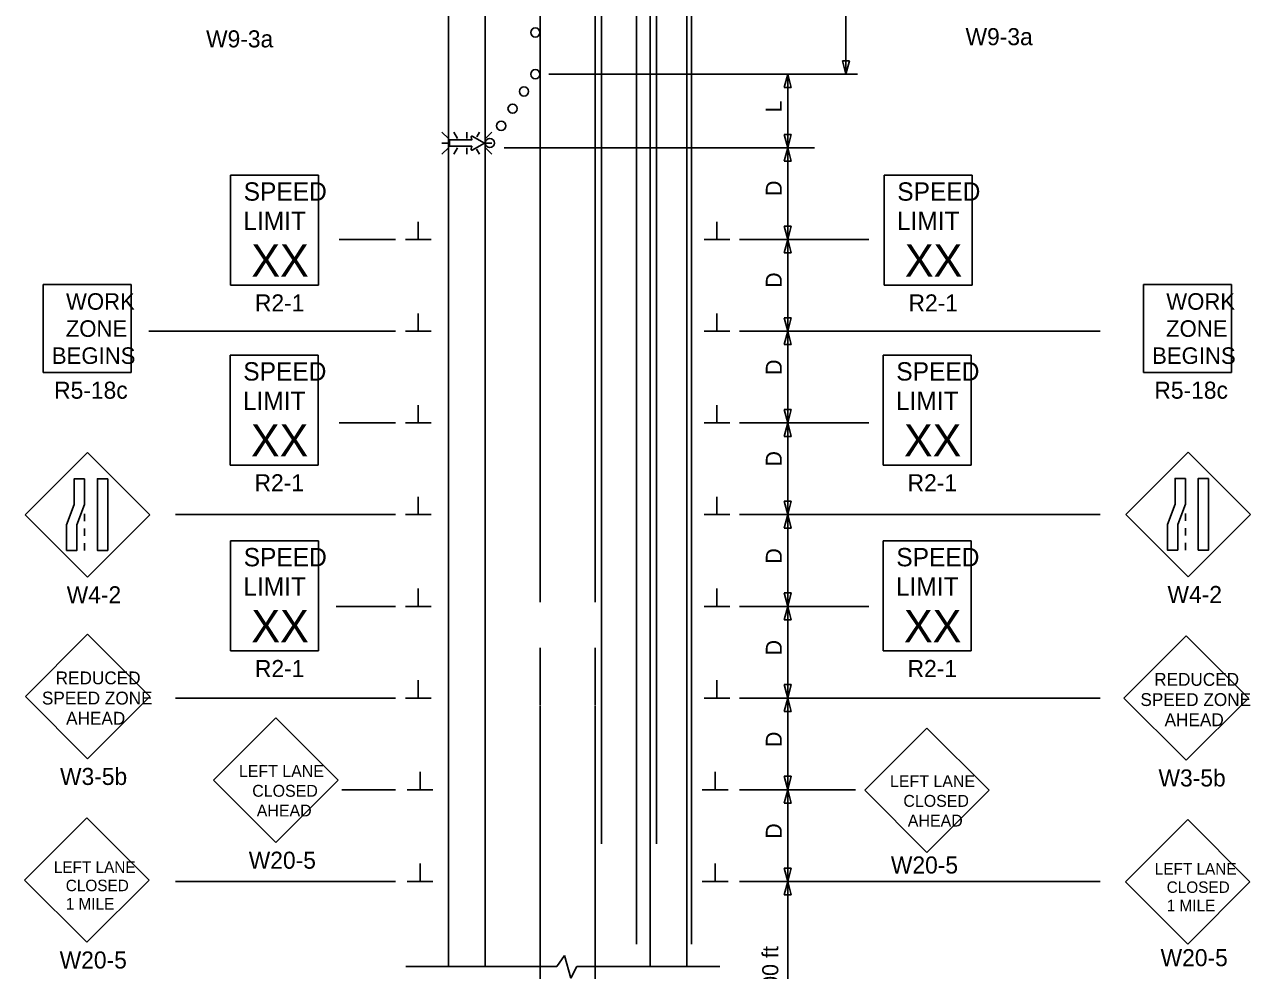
# Model space of a CAD drawing. Extents: x 16480 to 18482, y 7002 to 8333.
# Drawn here: x 16729 to 17264, y 7460 to 7872 of the extents above; entities that cross this region are included whole.
import ezdxf

# ---------------------------------------------------------------- set-up
doc = ezdxf.new("R2010")
doc.units = 0
for name, color, linetype in [('ALI_LEGAL_EX', 7, 'Continuous'), ('PAVT_EDGE_EX', 7, 'Continuous'), ('TRAFFIC_SIGNS_PR', 7, 'Continuous'), ('TYPICAL_TEXT_DIMEN_PR', 7, 'Continuous')]:
    doc.layers.add(name, color=color, linetype=linetype)

msp = doc.modelspace()

# ---------------------------------------------------------------- linework, layer by layer
at = {"layer": 'ALI_LEGAL_EX'}
for p, q in [((16980.68, 8333.08), (16980.68, 7514.94)), ((17004.68, 8333.08), (17004.68, 7514.94)), ((16995.95, 8289.26), (16995.95, 7471.12)), ((17019.95, 8289.26), (17019.95, 7471.12)), ((16953.87, 7620.35), (16953.87, 8241.48)), ((16977.87, 7620.35), (16977.87, 8241.48)), ((16953.87, 7497.94), (16953.87, 7575.09)), ((16977.87, 7497.94), (16977.87, 7575.09)), ((16953.87, 7379.99), (16953.87, 7560.8)), ((16977.87, 7379.99), (16977.87, 7560.8))]:
    msp.add_line(p, q, dxfattribs=at)
for points in [[(16953.87, 7775.35), (16953.87, 7800.35)], [(16977.87, 7775.35), (16977.87, 7800.35)], [(16953.87, 7675.35), (16953.87, 7700.35)], [(16977.87, 7675.35), (16977.87, 7700.35)], [(16953.87, 7575.35), (16953.87, 7600.35)], [(16977.87, 7575.35), (16977.87, 7600.35)], [(16953.87, 7475.35), (16953.87, 7500.35)], [(16977.87, 7475.35), (16977.87, 7500.35)]]:
    msp.add_lwpolyline(points, dxfattribs=at)
at = {"layer": 'PAVT_EDGE_EX'}
for p, q in [((16913.87, 8212.75), (16913.87, 7461.39)), ((16929.87, 8212.75), (16929.87, 7461.39)), ((17001.87, 8212.75), (17001.87, 7461.39)), ((17017.87, 8212.75), (17017.87, 7461.39))]:
    msp.add_line(p, q, dxfattribs=at)
at = {"layer": 'TRAFFIC_SIGNS_PR'}
for p, q in [((16913.89, 7822.57), (16911.06, 7825.39)), ((16916.18, 7825.39), (16917.81, 7822.57)), ((16921.97, 7822.57), (16921.97, 7825.39)), ((16927.44, 7825.39), (16926.23, 7823.3)), ((16932.87, 7825.39), (16930.06, 7822.57)), ((16913.89, 7820.54), (16911.06, 7820.54)), ((16913.89, 7818.5), (16911.06, 7815.68)), ((16917.83, 7818.5), (16916.21, 7815.68)), ((16921.97, 7818.5), (16921.97, 7815.68)), ((16930.06, 7820.54), (16932.87, 7820.54)), ((16932.87, 7815.69), (16930.06, 7818.5)), ((16926.15, 7817.87), (16927.41, 7815.68)), ((16818.81, 7806.57), (16857.21, 7806.57)), ((16818.81, 7758.57), (16818.81, 7806.57)), ((16857.21, 7758.57), (16857.21, 7806.57)), ((17103.89, 7806.57), (17142.29, 7806.57)), ((17103.89, 7758.57), (17103.89, 7806.57)), ((17142.29, 7758.57), (17142.29, 7806.57)), ((16737.08, 7720.5), (16737.08, 7758.9)), ((16737.08, 7758.9), (16775.48, 7758.9)), ((16775.48, 7720.5), (16775.48, 7758.9)), ((16818.81, 7758.57), (16857.21, 7758.57)), ((17103.89, 7758.57), (17142.29, 7758.57)), ((17217.01, 7720.5), (17217.01, 7758.9)), ((17217.01, 7758.9), (17255.41, 7758.9)), ((17255.41, 7720.5), (17255.41, 7758.9)), ((16818.63, 7728.12), (16857.03, 7728.12)), ((16818.63, 7680.12), (16818.63, 7728.12)), ((16857.03, 7680.12), (16857.03, 7728.12)), ((17103.48, 7728.12), (17141.88, 7728.12)), ((17103.48, 7680.12), (17103.48, 7728.12)), ((17141.88, 7680.12), (17141.88, 7728.12)), ((16737.08, 7720.5), (16775.48, 7720.5)), ((17217.01, 7720.5), (17255.41, 7720.5)), ((16756.41, 7685.57), (16729.26, 7658.42)), ((16783.57, 7658.42), (16756.41, 7685.57)), ((17236.59, 7685.7), (17209.43, 7658.55)), ((17263.74, 7658.55), (17236.59, 7685.7)), ((16818.63, 7680.12), (16857.03, 7680.12)), ((17103.48, 7680.12), (17141.88, 7680.12)), ((16729.26, 7658.42), (16756.41, 7631.26)), ((16755.17, 7658.91), (16755.17, 7655.71)), ((16756.41, 7631.26), (16783.57, 7658.42)), ((17209.43, 7658.55), (17236.59, 7631.39)), ((17235.34, 7659.04), (17235.34, 7655.84)), ((17236.59, 7631.39), (17263.74, 7658.55)), ((16755.17, 7652.51), (16755.17, 7649.31)), ((17235.34, 7652.64), (17235.34, 7649.44)), ((16818.81, 7647.1), (16857.21, 7647.1)), ((16818.81, 7599.1), (16818.81, 7647.1)), ((16857.21, 7599.1), (16857.21, 7647.1)), ((17103.48, 7647.1), (17141.88, 7647.1)), ((17103.48, 7599.1), (17103.48, 7647.1)), ((17141.88, 7599.1), (17141.88, 7647.1)), ((16755.17, 7646.11), (16755.17, 7642.91)), ((17235.34, 7646.24), (17235.34, 7643.04)), ((16756.51, 7606.33), (16729.36, 7579.18)), ((16783.66, 7579.18), (16756.51, 7606.33)), ((17235.67, 7605.68), (17208.52, 7578.52)), ((17262.82, 7578.52), (17235.67, 7605.68)), ((16818.81, 7599.1), (16857.21, 7599.1)), ((17103.48, 7599.1), (17141.88, 7599.1)), ((16729.36, 7579.18), (16756.51, 7552.03)), ((16756.51, 7552.03), (16783.66, 7579.18)), ((17208.52, 7578.52), (17235.67, 7551.37)), ((17235.67, 7551.37), (17262.82, 7578.52)), ((16838.61, 7569.8), (16811.46, 7542.65)), ((16865.76, 7542.65), (16838.61, 7569.8)), ((17122.61, 7565.41), (17095.46, 7538.26)), ((17149.77, 7538.26), (17122.61, 7565.41)), ((16811.46, 7542.65), (16838.61, 7515.49)), ((16838.61, 7515.49), (16865.76, 7542.65)), ((17095.46, 7538.26), (17122.61, 7511.1)), ((17122.61, 7511.1), (17149.77, 7538.26)), ((16756.13, 7526.26), (16728.98, 7499.11)), ((16783.29, 7499.11), (16756.13, 7526.26)), ((17236.36, 7525.51), (17209.21, 7498.35)), ((17263.51, 7498.35), (17236.36, 7525.51)), ((16728.98, 7499.11), (16756.13, 7471.95)), ((16756.13, 7471.95), (16783.29, 7499.11)), ((17209.21, 7498.35), (17236.36, 7471.2)), ((17236.36, 7471.2), (17263.51, 7498.35))]:
    msp.add_line(p, q, dxfattribs=at)
for points in [[(16924.3, 7817.52), (16929.61, 7820.54), (16924.3, 7823.58)], [(16923.8, 7823.22), (16924.03, 7821.92), (16914.3, 7821.92), (16914.3, 7819.18), (16924.03, 7819.18), (16923.8, 7817.88)]]:
    msp.add_lwpolyline(points, dxfattribs=at)
for points in [[(16755.17, 7674.15), (16755.17, 7662.97), (16751.82, 7654.09), (16751.82, 7642.91), (16747.33, 7642.91), (16747.33, 7654.09), (16750.67, 7662.97), (16750.67, 7674.15)], [(16765.3, 7674.15), (16765.3, 7642.91), (16760.81, 7642.91), (16760.81, 7674.15)], [(17235.34, 7674.28), (17235.34, 7663.1), (17231.99, 7654.22), (17231.99, 7643.04), (17227.5, 7643.04), (17227.5, 7654.22), (17230.84, 7663.1), (17230.84, 7674.28)], [(17245.47, 7674.28), (17245.47, 7643.04), (17240.98, 7643.04), (17240.98, 7674.28)]]:
    msp.add_lwpolyline(points, close=True, dxfattribs=at)
for centre in [(16951.8, 7868.82), (16951.8, 7850.6), (16946.83, 7843.09), (16941.87, 7835.59), (16936.9, 7828.08), (16931.93, 7820.58)]:
    msp.add_circle(centre, 2, dxfattribs=at)
for centre, start, end in [((16924.13, 7823.28), 61.4833, 189.9593), ((16924.13, 7817.82), 170.7308, 298.8916)]:
    msp.add_arc(centre, 0.341, start, end, dxfattribs=at)
at = {"layer": 'TYPICAL_TEXT_DIMEN_PR'}
for p, q in [((17087.3, 7968.48), (17087.3, 7850.6)), ((17087.3, 7850.6), (17085.73, 7856.46)), ((17085.73, 7856.46), (17087.3, 7856.46)), ((17087.3, 7856.46), (17088.87, 7856.46)), ((17088.87, 7856.46), (17087.3, 7850.6)), ((16957.62, 7850.6), (17066.87, 7850.6)), ((16957.62, 7850.6), (17092.3, 7850.6)), ((17060.3, 7844.74), (17061.87, 7850.6)), ((17061.87, 7850.6), (17061.87, 7818.5)), ((17061.87, 7850.6), (17063.44, 7844.74)), ((17061.87, 7844.74), (17060.3, 7844.74)), ((17063.44, 7844.74), (17061.87, 7844.74)), ((17061.87, 7818.5), (17060.3, 7824.36)), ((17060.3, 7824.36), (17061.87, 7824.36)), ((17061.87, 7824.36), (17063.44, 7824.36)), ((17063.44, 7824.36), (17061.87, 7818.5)), ((16938.26, 7818.5), (17066.87, 7818.5)), ((17073.63, 7818.5), (17021.17, 7818.5)), ((17060.3, 7812.64), (17061.87, 7818.5)), ((17061.87, 7818.5), (17061.87, 7778.5)), ((17061.87, 7818.5), (17063.44, 7812.64)), ((17061.87, 7812.64), (17060.3, 7812.64)), ((17063.44, 7812.64), (17061.87, 7812.64)), ((16900.74, 7778.5), (16900.74, 7786.28)), ((16900.74, 7778.5), (16900.74, 7786.28)), ((17030.99, 7778.5), (17030.99, 7786.28)), ((17061.87, 7778.5), (17060.3, 7784.36)), ((17060.3, 7784.36), (17061.87, 7784.36)), ((17061.87, 7784.36), (17063.44, 7784.36)), ((17063.44, 7784.36), (17061.87, 7778.5)), ((16866.23, 7778.5), (16890.87, 7778.5)), ((16866.23, 7778.5), (16890.87, 7778.5)), ((16895.12, 7778.5), (16906.37, 7778.5)), ((16895.12, 7778.5), (16906.37, 7778.5)), ((17036.62, 7778.5), (17025.37, 7778.5)), ((17097.31, 7778.5), (17040.87, 7778.5)), ((17060.3, 7772.64), (17061.87, 7778.5)), ((17061.87, 7778.5), (17061.87, 7738.5)), ((17061.87, 7778.5), (17063.44, 7772.64)), ((17061.87, 7772.64), (17060.3, 7772.64)), ((17063.44, 7772.64), (17061.87, 7772.64)), ((16900.74, 7738.5), (16900.74, 7746.28)), ((16900.74, 7738.5), (16900.74, 7746.28)), ((17030.99, 7738.5), (17030.99, 7746.28)), ((17061.87, 7738.5), (17060.3, 7744.36)), ((17060.3, 7744.36), (17061.87, 7744.36)), ((17061.87, 7744.36), (17063.44, 7744.36)), ((17063.44, 7744.36), (17061.87, 7738.5)), ((16783.24, 7738.5), (16890.87, 7738.5)), ((16864.87, 7738.5), (16890.87, 7738.5)), ((16895.12, 7738.5), (16906.37, 7738.5)), ((16895.12, 7738.5), (16906.37, 7738.5)), ((17036.62, 7738.5), (17025.37, 7738.5)), ((17198.2, 7738.5), (17040.87, 7738.5)), ((17060.3, 7732.64), (17061.87, 7738.5)), ((17061.87, 7738.5), (17061.87, 7698.5)), ((17061.87, 7738.5), (17063.44, 7732.64)), ((17061.87, 7732.64), (17060.3, 7732.64)), ((17063.44, 7732.64), (17061.87, 7732.64)), ((16900.74, 7698.5), (16900.74, 7706.28)), ((16900.74, 7698.5), (16900.74, 7706.28)), ((17030.99, 7698.5), (17030.99, 7706.28)), ((17061.87, 7698.5), (17060.3, 7704.36)), ((17060.3, 7704.36), (17061.87, 7704.36)), ((17061.87, 7704.36), (17063.44, 7704.36)), ((17063.44, 7704.36), (17061.87, 7698.5)), ((16866.23, 7698.5), (16890.87, 7698.5)), ((16878.29, 7698.5), (16890.87, 7698.5)), ((16895.12, 7698.5), (16906.37, 7698.5)), ((16895.12, 7698.5), (16906.37, 7698.5)), ((17036.62, 7698.5), (17025.37, 7698.5)), ((17097.31, 7698.5), (17040.87, 7698.5)), ((17060.3, 7692.64), (17061.87, 7698.5)), ((17061.87, 7698.5), (17063.44, 7692.64)), ((17061.87, 7698.5), (17061.87, 7658.5)), ((17061.87, 7692.64), (17060.3, 7692.64)), ((17063.44, 7692.64), (17061.87, 7692.64)), ((16900.74, 7658.5), (16900.74, 7666.28)), ((16900.74, 7658.5), (16900.74, 7666.28)), ((17030.99, 7658.5), (17030.99, 7666.28)), ((17061.87, 7658.5), (17060.3, 7664.36)), ((17060.3, 7664.36), (17061.87, 7664.36)), ((17061.87, 7664.36), (17063.44, 7664.36)), ((17063.44, 7664.36), (17061.87, 7658.5)), ((16794.77, 7658.5), (16890.87, 7658.5)), ((16864.87, 7658.5), (16890.87, 7658.5)), ((16895.12, 7658.5), (16906.37, 7658.5)), ((16895.12, 7658.5), (16906.37, 7658.5)), ((17036.62, 7658.5), (17025.37, 7658.5)), ((17198.2, 7658.5), (17040.87, 7658.5)), ((17060.3, 7652.64), (17061.87, 7658.5)), ((17061.87, 7658.5), (17061.87, 7618.5)), ((17061.87, 7658.5), (17063.44, 7652.64)), ((17061.87, 7652.64), (17060.3, 7652.64)), ((17063.44, 7652.64), (17061.87, 7652.64)), ((16900.74, 7618.5), (16900.74, 7626.28)), ((17030.99, 7618.5), (17030.99, 7626.28)), ((17061.87, 7618.5), (17060.3, 7624.36)), ((17060.3, 7624.36), (17061.87, 7624.36)), ((17061.87, 7624.36), (17063.44, 7624.36)), ((17063.44, 7624.36), (17061.87, 7618.5)), ((16864.87, 7618.5), (16890.87, 7618.5)), ((16895.12, 7618.5), (16906.37, 7618.5)), ((17036.62, 7618.5), (17025.37, 7618.5)), ((17097.31, 7618.5), (17040.87, 7618.5)), ((17060.3, 7612.64), (17061.87, 7618.5)), ((17061.87, 7618.5), (17061.87, 7578.5)), ((17061.87, 7618.5), (17063.44, 7612.64)), ((17061.87, 7612.64), (17060.3, 7612.64)), ((17063.44, 7612.64), (17061.87, 7612.64)), ((16900.74, 7578.5), (16900.74, 7586.28)), ((17030.99, 7578.5), (17030.99, 7586.28)), ((17061.87, 7578.5), (17060.3, 7584.36)), ((17060.3, 7584.36), (17061.87, 7584.36)), ((17061.87, 7584.36), (17063.44, 7584.36)), ((17063.44, 7584.36), (17061.87, 7578.5)), ((16794.77, 7578.5), (16890.87, 7578.5)), ((16895.12, 7578.5), (16906.37, 7578.5)), ((17036.62, 7578.5), (17025.37, 7578.5)), ((17198.2, 7578.5), (17040.87, 7578.5)), ((17060.3, 7572.64), (17061.87, 7578.5)), ((17061.87, 7578.5), (17061.87, 7538.5)), ((17061.87, 7578.5), (17063.44, 7572.64)), ((17061.87, 7572.64), (17060.3, 7572.64)), ((17063.44, 7572.64), (17061.87, 7572.64)), ((16901.49, 7538.5), (16901.49, 7546.28)), ((17030.24, 7538.5), (17030.24, 7546.28)), ((17061.87, 7538.5), (17060.3, 7544.36)), ((17060.3, 7544.36), (17061.87, 7544.36)), ((17061.87, 7544.36), (17063.44, 7544.36)), ((17063.44, 7544.36), (17061.87, 7538.5)), ((16867.38, 7538.5), (16890.87, 7538.5)), ((16895.87, 7538.5), (16907.12, 7538.5)), ((17035.87, 7538.5), (17024.62, 7538.5)), ((17091.49, 7538.5), (17040.87, 7538.5)), ((17060.3, 7532.64), (17061.87, 7538.5)), ((17061.87, 7538.5), (17061.87, 7498.5)), ((17061.87, 7538.5), (17063.44, 7532.64)), ((17061.87, 7532.64), (17060.3, 7532.64)), ((17063.44, 7532.64), (17061.87, 7532.64)), ((16901.49, 7498.5), (16901.49, 7506.28)), ((17030.24, 7498.5), (17030.24, 7506.28)), ((17061.87, 7498.5), (17060.3, 7504.36)), ((17060.3, 7504.36), (17061.87, 7504.36)), ((17061.87, 7504.36), (17063.44, 7504.36)), ((17063.44, 7504.36), (17061.87, 7498.5)), ((16794.77, 7498.5), (16890.87, 7498.5)), ((16895.87, 7498.5), (16907.12, 7498.5)), ((17035.87, 7498.5), (17024.62, 7498.5)), ((17198.2, 7498.5), (17040.87, 7498.5)), ((17060.3, 7492.64), (17061.87, 7498.5)), ((17061.87, 7498.5), (17061.87, 7416.94)), ((17061.87, 7498.5), (17063.44, 7492.64)), ((17061.87, 7492.64), (17060.3, 7492.64)), ((17063.44, 7492.64), (17061.87, 7492.64)), ((16964.47, 7466.19), (16961.21, 7461.39)), ((16967.21, 7456.25), (16964.47, 7466.19)), ((16961.21, 7461.39), (16895.27, 7461.39)), ((16969.95, 7461.39), (16967.21, 7456.25)), ((17032.29, 7461.39), (16969.95, 7461.39))]:
    msp.add_line(p, q, dxfattribs=at)

# ---------------------------------------------------------------- texts
at = {"layer": 'TRAFFIC_SIGNS_PR'}
for s, height, p in [('W9-3a', 7.44, (16808.17, 7862.3)), ('W9-3a', 7.44, (17139.45, 7863.27)), ('SPEED', 8, (16824.58, 7795.44)), ('SPEED', 8, (17109.66, 7795.44)), ('LIMIT', 8, (16824.42, 7782.64)), ('LIMIT', 8, (17109.5, 7782.64)), ('XX', 14.031, (16827.93, 7762.33)), ('XX', 14.031, (17113, 7762.33)), ('WORK', 7.217, (16747.08, 7747.87)), ('R2-1', 7.44, (16829.49, 7747.13)), ('R2-1', 7.44, (17114.57, 7747.13)), ('WORK', 7.217, (17227.01, 7747.87)), ('ZONE', 7.217, (16746.97, 7736.06)), ('ZONE', 7.217, (17226.89, 7736.06)), ('BEGINS', 7.217, (16740.9, 7724.25)), ('BEGINS', 7.217, (17220.82, 7724.25)), ('SPEED', 8, (16824.4, 7716.99)), ('SPEED', 8, (17109.25, 7716.99)), ('R5-18c', 7.44, (16741.9, 7709.06)), ('R5-18c', 7.44, (17221.82, 7709.06)), ('LIMIT', 8, (16824.23, 7704.19)), ('LIMIT', 8, (17109.08, 7704.19)), ('XX', 14.031, (16827.74, 7683.88)), ('XX', 14.031, (17112.59, 7683.88)), ('R2-1', 7.44, (16829.31, 7668.68)), ('R2-1', 7.44, (17114.16, 7668.68)), ('SPEED', 8, (16824.58, 7635.96)), ('SPEED', 8, (17109.25, 7635.96)), ('LIMIT', 8, (16824.42, 7623.16)), ('LIMIT', 8, (17109.08, 7623.16)), ('W4-2', 7.44, (16747.37, 7619.82)), ('W4-2', 7.44, (17227.54, 7619.95)), ('XX', 14.031, (16827.93, 7602.86)), ('XX', 14.031, (17112.59, 7602.86)), ('R2-1', 7.44, (16829.49, 7587.66)), ('R2-1', 7.44, (17114.16, 7587.66)), ('REDUCED', 5.6, (16742.57, 7584.49)), ('REDUCED', 5.6, (17221.73, 7583.83)), ('SPEED ZONE', 5.6, (16736.56, 7575.69)), ('SPEED ZONE', 5.6, (17215.72, 7575.03)), ('AHEAD', 5.6, (16747.12, 7566.89)), ('AHEAD', 5.6, (17226.28, 7566.23)), ('W3-5b', 7.44, (16744.46, 7540.59)), ('LEFT LANE', 5.2, (16822.49, 7544.04)), ('W3-5b', 7.44, (17223.62, 7539.93)), ('CLOSED', 5.2, (16828.32, 7535.44)), ('LEFT LANE', 5.2, (17106.5, 7539.65)), ('CLOSED', 5.2, (17112.33, 7531.05)), ('AHEAD', 5.2, (16830.27, 7526.84)), ('AHEAD', 5.2, (17114.27, 7522.45)), ('W20-5', 7.44, (16826.78, 7504.05)), ('W20-5', 7.44, (17106.88, 7501.97)), ('LEFT LANE', 5, (16741.76, 7502.26)), ('LEFT LANE', 5, (17221.99, 7501.51)), ('CLOSED', 5, (16746.97, 7494.26)), ('CLOSED', 5, (17227.19, 7493.51)), ('1 MILE', 5, (16746.96, 7486.26)), ('1 MILE', 5, (17227.19, 7485.51)), ('W20-5', 7.44, (16744.31, 7460.52)), ('W20-5', 7.44, (17224.53, 7461.54))]:
    msp.add_text(s, height=height, dxfattribs=at).set_placement(p)
at = {"layer": 'TYPICAL_TEXT_DIMEN_PR'}
for s, p in [('L', (17059.31, 7833.91)), ('D', (17059.31, 7797.46)), ('D', (17059.31, 7757.4)), ('D', (17059.31, 7719.42)), ('D', (17059.31, 7679.47)), ('D', (17059.31, 7637.09)), ('D', (17059.31, 7597.09)), ('D', (17059.31, 7557.09)), ('D', (17059.31, 7517.09)), ('5300 ft', (17057.78, 7441.66))]:
    msp.add_text(s, height=7, rotation=90, dxfattribs=at).set_placement(p)

doc.saveas('drawing.dxf')
